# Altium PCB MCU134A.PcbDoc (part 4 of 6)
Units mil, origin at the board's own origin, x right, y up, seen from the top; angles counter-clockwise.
Board outline 4163.98 x 2693.8 mil, 6 copper layers (Top Layer, GND1, SIG1, PWR, GND2, Bottom), stack 58.132 mil thick; 218 components, 287 nets, 1260 pads, 770 vias.
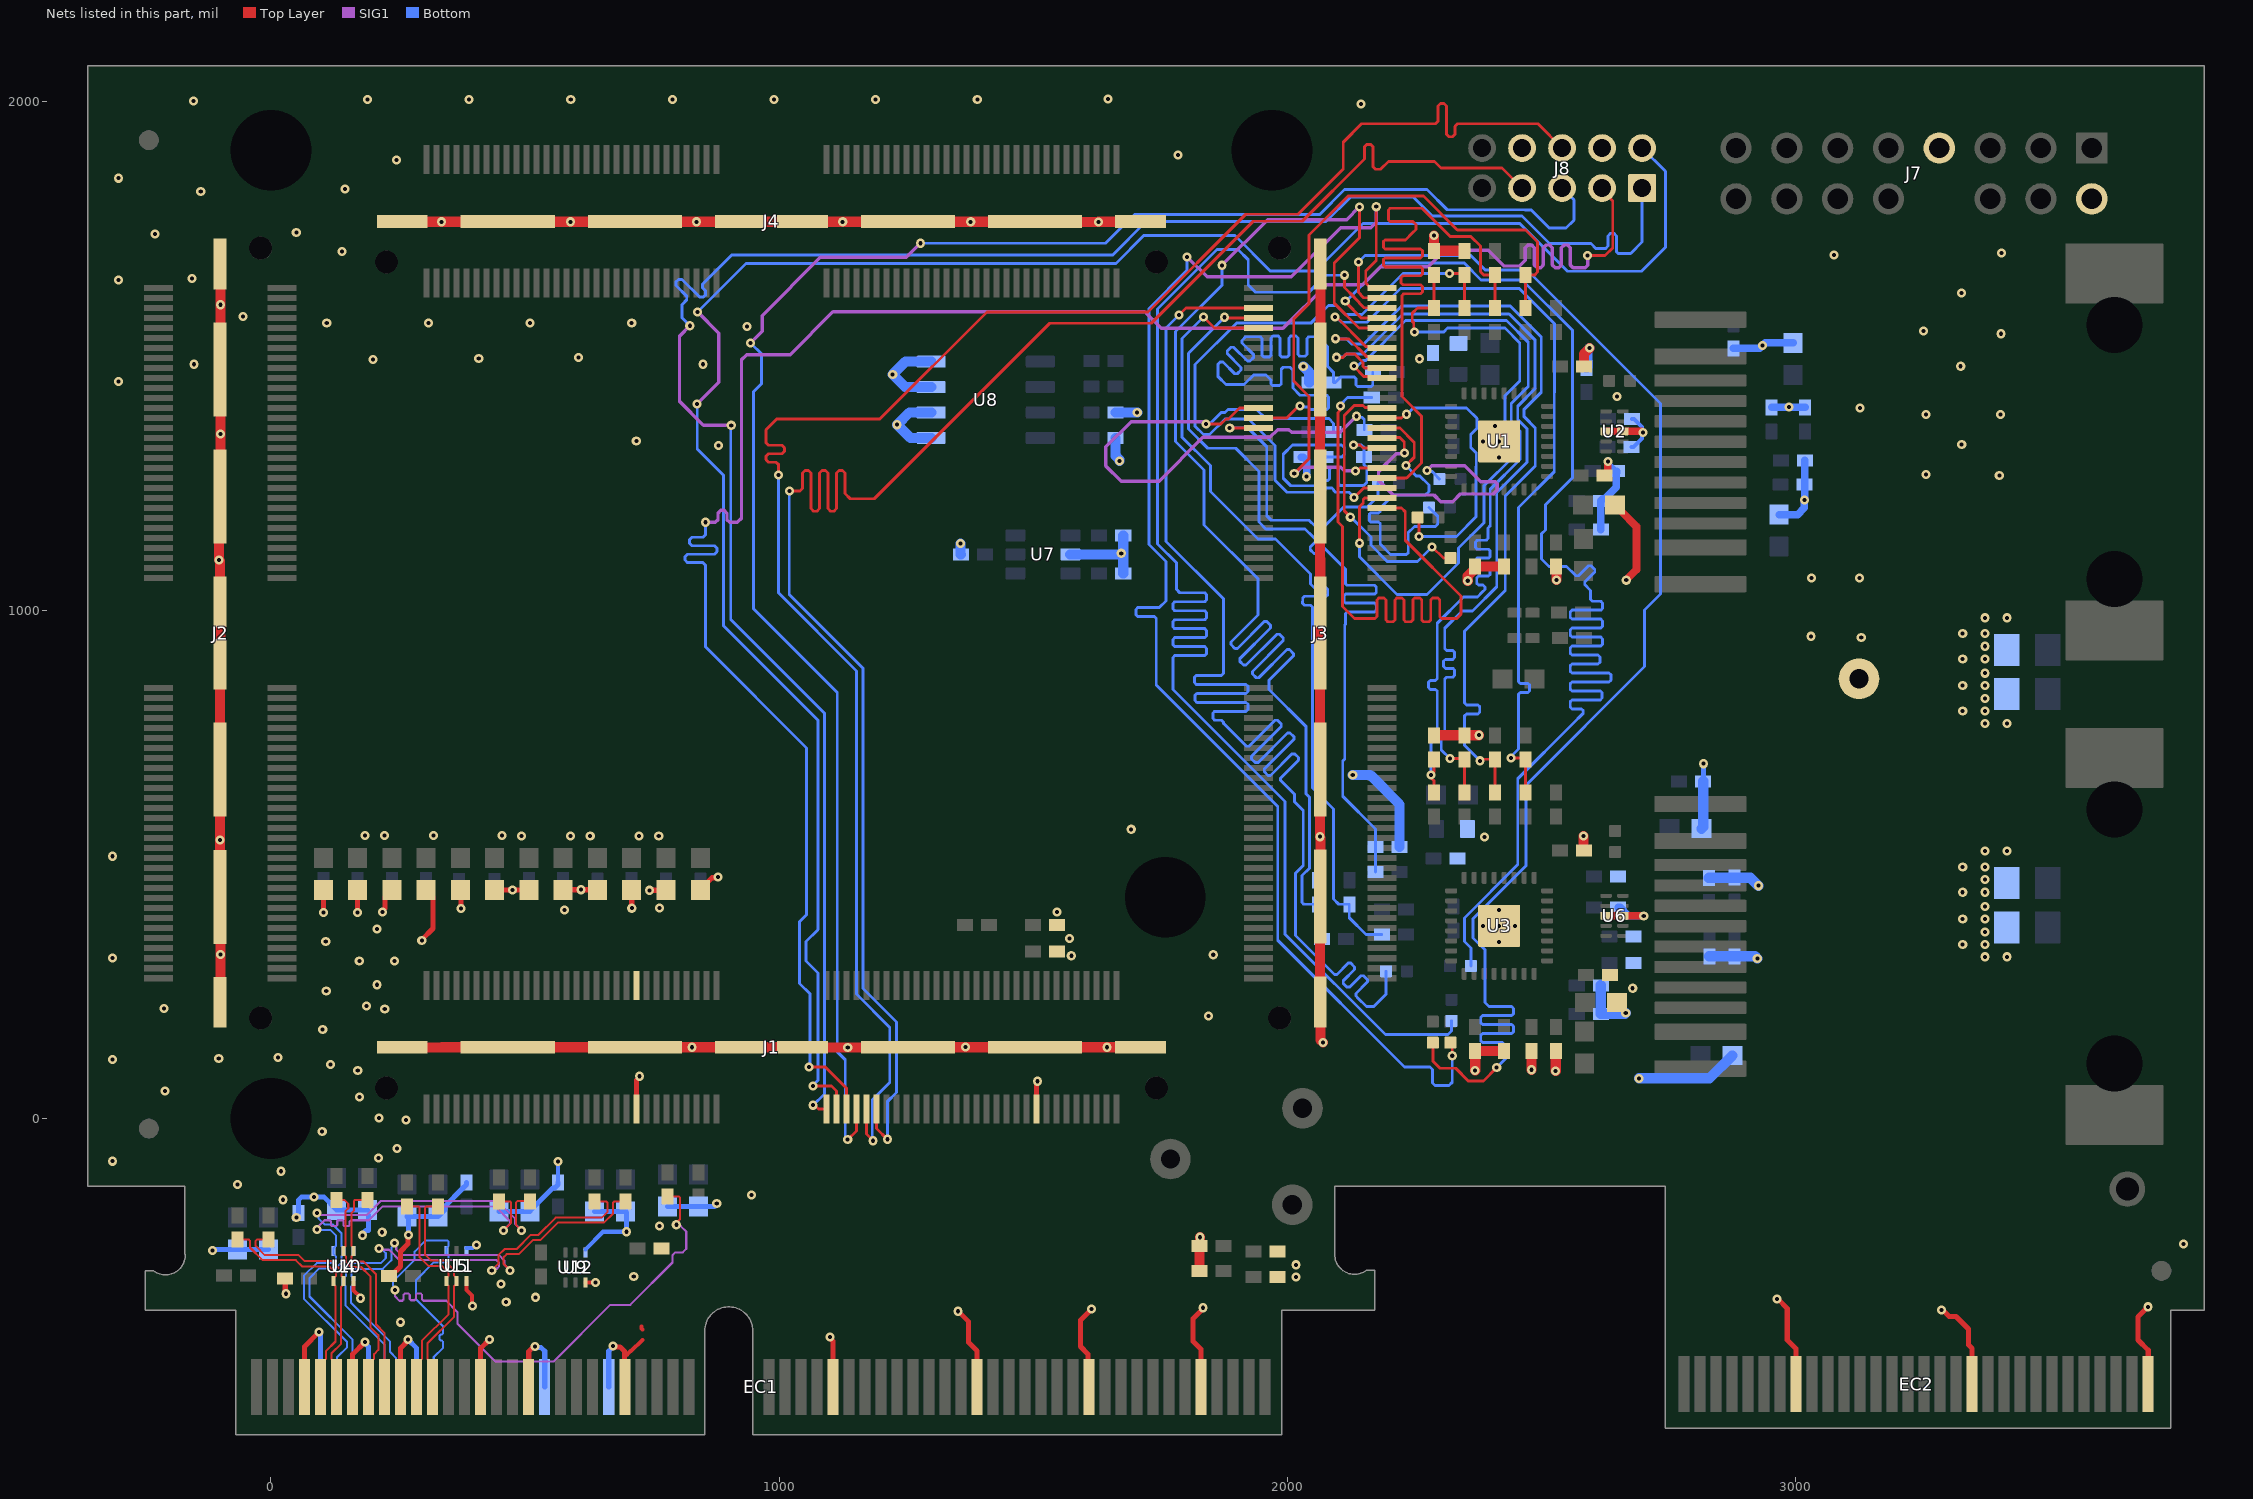
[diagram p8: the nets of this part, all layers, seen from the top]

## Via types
v1: diameter 18, hole 8, Top Layer to Bottom, tented both sides, 761 vias
v2: diameter 19.68, hole 7.87, Top Layer to Bottom, tented both sides, 9 vias

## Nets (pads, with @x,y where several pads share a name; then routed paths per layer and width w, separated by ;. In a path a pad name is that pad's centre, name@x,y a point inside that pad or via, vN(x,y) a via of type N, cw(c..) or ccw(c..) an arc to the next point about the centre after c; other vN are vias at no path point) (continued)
ESC_RX0_DATA0: J3.102 R78.1 R86.2 | length 1646.9
  Top Layer w5.66: v1(2131.17,1480.17) 2131.17,1479.24 2150.28,1460.14 2183.32,1460.14 J3.102@2186.5,1456.97 ; R78.1@2288.47,641.6 2289,642.12 2289,663.98 2283,669.98 2283,676.34 2289,682.34 2289,706.07 R86.2@2288.47,706.6
  Bottom w5.66: v1(2131.17,1480.17) 2133.54,1482.54 2140.02,1482.54 2149.11,1491.62 2154.5,1491.62 2232.87,1570 2431.3,1570 2474.18,1527.12 2474.18,1440.1 2440.76,1406.68 2440.76,1370.14 2458,1352.9 2458,1296.65 2399.37,1238.02 2399.37,1166.18 2394.87,1161.68 2394.87,1141.19 2391.34,1137.66 2373.77,1137.66 2370.24,1134.13 2370.24,1123.53 2373.77,1120 2395.66,1120 2399.19,1116.47 2399.19,1105.87 2395.66,1102.34 2373.77,1102.34 2370.24,1098.81 2370.24,1088.21 2373.77,1084.68 2395.66,1084.68 2399.19,1081.15 2399.19,1070.55 2395.66,1067.02 2376.36,1067.02 2372.83,1063.49 2372.83,1052.89 2376.36,1049.36 2385.3,1049.36 2388.84,1045.83 2388.84,1040.83 2383.29,1035.28 2374,1026 2346.65,1026 2294.99,974.35 2294.99,898.21 2294.99,865.43 2291.46,861.89 2281.44,861.89 2277.91,858.36 2277.91,847.77 2281.44,844.23 2291.46,844.23 2294.99,840.7 2294.99,837.87 2294.99,761.6 2283,749.61 v1(2283,675.99)
ESC_RX0_DATA1: J3.104 R70.1 R84.2 | length 1647.9
  Top Layer w5.66: v1(2097.1,1497.6) 2109.46,1497.6 2115.69,1503.83 2132.77,1503.83 2149,1487.59 2149,1479.97 2152.32,1476.65 J3.104@2186.5,1476.65 ; v1(2320,708) 2347.07,708 R84.2@2348.47,706.6 R70.1@2348.47,641.6
  Bottom w5.66: v1(2097.1,1497.6) 2098.27,1498.77 2110.63,1498.77 2116.14,1504.28 2149.25,1504.28 2227.63,1582.66 2436.55,1582.66 2487.03,1532.18 2487.03,1434.96 2453.42,1401.36 2453.42,1375.38 2472,1356.81 2472,1291.61 2412.03,1231.64 2412.03,1046.12 2364.59,998.68 2343.87,998.68 2309.7,964.51 2309.7,927.28 2309.7,924.45 2313.23,920.92 2325.57,920.92 2329.1,917.39 2329.1,906.79 2325.57,903.26 2311.19,903.26 2307.65,899.73 2307.65,889.13 2311.19,885.6 2325.57,885.6 2329.1,882.07 2329.1,871.47 2325.57,867.94 2313.23,867.94 2309.7,864.41 2309.7,833.64 2309.7,752.55 2303.04,745.88 2303.04,724.96 v1(2320,708)
ESC_RX0_DATA2: J3.106 R63.1 R71.1 | length 1645.9
  Top Layer w5.66: v1(2095,1534.26) 2095.93,1533.33 2121.64,1533.33 2155.46,1499.51 2183.32,1499.51 J3.106@2186.5,1496.34 ; v1(2379,703.68) 2382.34,703.68 2385.25,706.6 R63.1@2408.47,706.6 R71.1@2408.47,641.6
  Bottom w5.66: v1(2095,1534.26) 2095.93,1533.33 2117.03,1533.33 2126.24,1524.11 2151.18,1524.11 2225.98,1598.91 2438.2,1598.91 2499.69,1537.42 2499.69,1429 2466.08,1395.4 2466.08,1380.63 2488,1358.71 2488,1283.6 2428.83,1224.43 2428.83,1038.91 2419.49,1029.57 2419.49,1029.39 2349,958.9 2349,819.98 2349,817.15 2352.53,813.62 2375.08,813.62 2378.61,810.09 2378.61,799.49 2375.08,795.96 2352.53,795.96 2349,792.43 2349,788.66 2349,733.68 v1(2379,703.68)
ESC_RX0_DATA3: J3.108 R62.1 R72.1 | length 1628.1
  Top Layer w5.66: v1(2093.76,1576.74) 2096.86,1576.74 2154.42,1519.18 2183.34,1519.18 J3.108@2186.5,1516.02 ; v1(2440,709) 2462.49,709 2468.47,703.02 R72.1@2468.47,641.6
  Bottom w5.66: v1(2093.76,1576.74) 2097.1,1576.74 2107.31,1566.53 2156.59,1566.53 2222.92,1632.87 2456.41,1632.87 2525.56,1563.72 2525.56,1428.32 2525.19,1427.96 2525.19,1272.25 2455,1202.05 2455,862.2 2455,859.37 2458.53,855.84 2473.36,855.84 2476.89,852.31 2476.89,841.71 2473.36,838.18 2458.53,838.18 2455,834.65 2455,819.98 2455,785.34 2455,727 2440,712 v1(2440,709)
ESC_RX0_DV: J3.113 R68.1 R85.2 | length 1691.2
  Top Layer w5.66: v1(1876.53,1576.48) 1877.93,1575.09 J3.113@1943.5,1575.08
  Bottom w5.66: v1(1876.53,1576.48) 1805.51,1505.46 1805.51,1356.49 1843.38,1318.62 1898.68,1318.62 1944.24,1273.07 1944.24,1173.51 1957.74,1160 2035.13,1160 2049.97,1145.16 2055.6,1139.53 2055.6,1134.54 2045.12,1124.06 2045.12,1119.07 2052.62,1111.58 2057.61,1111.58 2068.08,1122.05 2073.08,1122.05 2075.08,1120.05 2114.2,1080.93 2114.2,1064.8 2114.2,1052.71 2117.73,1049.18 2171.46,1049.18 2174.99,1045.65 2174.99,1035.05 2171.46,1031.52 2114.75,1031.52 2111.22,1027.99 2111.22,1017.39 2114.75,1013.86 2171.46,1013.86 2174.99,1010.33 2174.99,999.73 2171.46,996.2 2117.73,996.2 2114.2,992.67 2114.2,972.18 2113.12,971.1 2113.12,707.31 2109.03,703.22 2109.03,679.76 2109,634 2173.68,569.32 R85.2@2173.68,534.38 2173.24,533.93 R68.1@2173.24,485.04
ESC_RX0_ERR: J3.111 R61.1 R73.1 | length 1649.7
  Top Layer w5.66: v1(1835.24,1576.87) 1856.72,1555.39 J3.111@1943.5,1555.39
  Bottom w5.66: v1(1835.24,1576.87) 1792.85,1534.48 1792.85,1340.42 1848.8,1284.46 1848.8,1233.83 1942.64,1140 1976.68,1140 2045.53,1071.14 2045.53,1051.65 2048.4,1048.78 2048.8,1048.38 2052.29,1044.8 2076.2,1044.5 2079.69,1040.93 2079.56,1030.33 2075.98,1026.84 2033.95,1027.37 2030.38,1023.88 2030.25,1013.28 2033.73,1009.71 2046.29,1009.55 2049.78,1005.98 2049.78,1003.15 2049.78,650.22 2091,609 2091,431.63 2101.25,421.38 R61.1@2122,421.38 2122,394.76 2155.05,361.72 R73.1@2185.9,361.72
ESC_RX1_CLK: J3.76 R9.1 | length 1338.3
  Top Layer w5.66: v1(2105,1402.03) 2102.64,1399.67 2102.64,1391.76 2099.51,1388.63 2099.51,1173.78 2108.91,1164.38 2108.91,1007.26 2132.39,983.77 2162.46,983.77 2172.83,983.77 2176.36,987.31 2176.36,1020.24 2179.89,1023.77 2190.49,1023.77 2194.02,1020.24 2194.02,980.85 2197.55,977.32 2208.15,977.32 2211.68,980.85 2211.68,1020.24 2215.21,1023.77 2225.81,1023.77 2229.34,1020.24 2229.34,980.85 2232.87,977.32 2243.47,977.32 2247,980.85 2247,1020.24 2250.53,1023.77 2261.13,1023.77 2264.66,1020.24 2264.66,980.85 2268.19,977.32 2278.79,977.32 2282.32,980.85 2282.32,1020.24 2285.85,1023.77 2296.45,1023.77 2299.98,1020.24 2299.98,987.31 2303.51,983.77 2324,983.77 2333.58,983.77 2342,992.2 2342,1027.73 2232.17,1137.56 2232.17,1193.73 2224.84,1201.06 J3.76@2186.5,1201.06
  Bottom w5.66: v1(2105,1402.03) 2105,1405 2118.51,1418.51 R9.1@2166.16,1418.51
ESC_RX1_DATA0: J3.78 R24.1 R31.2 | length 1274.5
  Top Layer w5.66: v1(2141.82,1131.82) 2141.82,1203.42 2149.41,1211.01 2149.41,1217.92 2152.24,1220.75 J3.78@2186.5,1220.75 ; v1(2250.44,1547.6) 2248.7,1549.34 2248.7,1565.57 2245.87,1568.4 2245.87,1584.44 2256.31,1594.88 R24.1@2288.47,1594.88 R31.2@2288.47,1659.88
  Bottom w5.66: v1(2141.82,1131.82) 2141.82,1105.19 2216,1031 2275,1031 2337.17,1093.17 2337.17,1122.17 2386.71,1171.71 2386.71,1244.16 2444,1301.46 2444,1349 2428.1,1364.9 2428.1,1421.9 2457.44,1451.23 2457.44,1525.96 2428.4,1555 2315.33,1555 2307.93,1547.6 v1(2250.44,1547.6)
ESC_RX1_DATA1: J3.80 R15.1 R29.2 | length 1313.5
  Top Layer w5.66: v1(2131.58,1221.72) 2150.29,1240.43 J3.80@2186.5,1240.43 ; v1(2319.14,1662.33) 2346.02,1662.33 R29.2@2348.47,1659.88 R15.1@2348.47,1594.88
  Bottom w5.66: v1(2131.58,1221.72) 2121.19,1232.12 2115.45,1232.12 2094.96,1232.12 2091.42,1235.65 2091.42,1236.7 2087.89,1240.23 2077.3,1240.23 2073.76,1236.7 2073.76,1235.65 2070.23,1232.12 2064.32,1232.12 1999.28,1232.12 1975.54,1255.86 1975.54,1324.31 1923.5,1376.34 1877.96,1376.34 1847.11,1345.49 1834.96,1345.49 1818.51,1361.94 1818.51,1483.38 1899.88,1564.75 2046.13,1564.75 2080.82,1599.43 2096.28,1599.43 2113.85,1581.86 2147.26,1581.86 2227.73,1662.33 v1(2319.14,1662.33)
ESC_RX1_DATA2: J3.82 R8.1 R16.1 | length 1392.8
  Top Layer w5.66: J3.82@2186.5,1260.12 2234.9,1260.12 2264.35,1289.56 2264.35,1381.62 2225.64,1420.34 2225.64,1598.63 2225.64,1619.13 2229.17,1622.66 2262.38,1622.66 2265.91,1626.19 2265.91,1636.79 2262.38,1640.32 2227.4,1640.32 2223.87,1643.85 2223.87,1654.45 2227.4,1657.98 2262.38,1657.98 2265.91,1661.51 2265.91,1672.11 2262.38,1675.64 2192.47,1675.64 2188.94,1679.17 2188.94,1689.77 2192.47,1693.3 2262.38,1693.3 2265.91,1696.83 2265.91,1707.43 2262.38,1710.96 2192.47,1710.96 2188.94,1714.49 2188.94,1725.09 2192.47,1728.62 2232.36,1728.62 2246.38,1742.64 2253,1749.26 2253,1759 2247,1765 2202.32,1765 2199,1768.32 2199,1787.68 2202.32,1791 2265,1791 2320.49,1735.51 2361.01,1735.51 2380,1716.51 2380,1666.11 2386.24,1659.88 R8.1@2408.47,1659.88 R16.1@2408.47,1594.88
ESC_RX1_DATA3: J3.84 R7.1 R17.1 | length 1358.6
  Top Layer w5.66: v1(2013.69,1268.92) 2042.83,1298.06 2042.83,1420.79 2012.67,1450.95 2012.67,1572.67 2042.83,1602.83 2042.83,1737.99 2119.9,1815.06 2267.68,1815.06 2334.58,1748.17 2468.83,1748.17 2492.62,1724.38 2492.62,1665.39 2487.11,1659.88 R7.1@2468.47,1659.88 R17.1@2468.47,1594.88 ; v1(2133.97,1274.04) 2137.31,1274.04 2143.07,1279.8 J3.84@2186.5,1279.8
  SIG1 w6.66: v1@2013.97,1268.92 2016.76,1268.92 2028.82,1280.98 2105.21,1280.98 2112.14,1274.04 v1(2133.97,1274.04)
ESC_RX1_DV: J3.93 R13.1 R30.2 | length 1335.9
  Top Layer w5.66: J3.93@1943.5,1378.23 1998.87,1378.23 2022.75,1402.12 v1(2025,1402.12)
  Bottom w5.66: v1(2025,1402.12) 2027.36,1399.76 2040.56,1399.76 2045.32,1395 2077.68,1395 2081,1398.32 2081,1419.68 2077.68,1423 2025,1423 2011,1437 2011,1472 2005,1478 1992,1478 1988,1474 1988,1445.25 1984.68,1441.94 1971.32,1441.94 1968,1445.25 1968,1453 1958.04,1462.96 1933.96,1462.96 1915,1444 1879.32,1444 1864,1459.32 1864,1468.7 1864,1484.34 1864.64,1484.98 1868.17,1488.51 1873.17,1488.51 1896.46,1465.22 1901.45,1465.22 1908.94,1472.71 1908.94,1477.71 1881.76,1504.89 1881.76,1509.88 1889.26,1517.37 1894.25,1517.37 1921.43,1490.2 1926.43,1490.2 1933.92,1497.69 1933.92,1502.68 1910.63,1525.97 1910.63,1530.97 1917.66,1538 1926.28,1538 1946.77,1538 1950.3,1534.47 1950.3,1501.53 1953.83,1498 1964.43,1498 1967.96,1501.53 1967.96,1535.89 1971.49,1539.43 1982.09,1539.43 1985.62,1535.89 1985.62,1501.53 1989.15,1498 1999.75,1498 2003.28,1501.53 2003.28,1535.89 2006.81,1539.43 2017.41,1539.43 2020.94,1535.89 2020.94,1503.12 2024.47,1499.59 2035.07,1499.59 2038.6,1503.12 2038.6,1534.47 2042.13,1538 2060,1538 2063,1535 2078.88,1519.12 2078.88,1479.97 2090.55,1468.3 R30.2@2090.55,1448 2094.49,1448 2105.25,1458.75 2131.68,1458.75 2135,1455.44 2135,1442.83 2137.83,1440 2165.4,1440 2168.23,1442.83 R13.1@2168.23,1468.23
ESC_RX1_ERR: J3.95 R6.1 R18.1 | length 1265.7
  Top Layer w5.66: v1(1840.06,1366.3) 1869.22,1366.3 1879.25,1376.34 1884.51,1376.34 1906.03,1397.86 J3.95@1943.46,1397.86
  SIG1 w6.66: v1(1840.06,1366.3) 1835.59,1370.78 1692.59,1370.78 1643.1,1321.29 1643.1,1283.76 1672.81,1254.04 1747.91,1254.04 1834.05,1340.18 1965.86,1340.18 1980.96,1355.28 2003,1355.28 2008.44,1349.84 2103.84,1349.84 2135.6,1381.6 v1(2136.41,1381.6)
  Bottom w5.66: v1(1840.06,1366.3) 1847.38,1366.3 1870.08,1389 1877.53,1389 1883.53,1395 1939.61,1395 1957.56,1377.06 2081.75,1377.06 2091.18,1367.62 R6.1@2091.18,1350.43 ; v1(2136.41,1381.6) 2138.37,1379.64 2146.83,1379.64 2151.46,1375.01 R18.1@2151.46,1354.96
ESC_TX0_CLK: J3.112 R74.1 R83.2 | length 2694.6
  Top Layer w5.66: v1(2141.96,1793.67) 2141.96,1732.85 2092.31,1683.2 2092.31,1603.91 2140.82,1555.39 J3.112@2186.5,1555.39
  SIG1 w6.66: v1(1871.38,1678.62) 1961.13,1768.38 2116.66,1768.38 v1(2141.96,1793.67)
  Bottom w5.66: v1(1871.38,1678.62) 1871.38,1639.46 1780.19,1548.27 1780.19,1331.81 1836.14,1275.86 1836.14,1167.86 1942.16,1061.84 1942.16,990.25 1889.27,937.36 1889.27,932.36 1896.76,924.87 1901.75,924.87 1954.65,977.76 1959.64,977.76 1967.13,970.27 1967.13,965.27 1906.36,904.5 1906.36,899.5 1913.85,892.01 1918.84,892.01 1979.62,952.79 1984.62,952.79 1992.11,945.29 1992.11,940.3 1931.33,879.52 1931.33,874.53 1938.82,867.03 1943.82,867.03 1999.35,922.57 2004.35,922.57 2011.84,915.08 2011.84,910.08 1964.04,862.28 1964.04,843.79 2037.12,770.71 2037.12,638.12 2043.99,631.25 2043.99,492.66 2029,477.67 2029,424.69 2032.32,421.38 R83.2@2060,421.38 2060,391 2068.61,382.4 R74.1@2068.61,352.87
ESC_TX0_DATA0: J3.114 R69.2 | length 2834.9
  Top Layer w5.66: v1(2114.01,1608.33) 2114.01,1606.8 2145.62,1575.19 2150.96,1575.19 2151.07,1575.08 J3.114@2186.5,1575.08
  Bottom w5.66: v1(2114.01,1608.33) 2116.12,1608.33 2191.31,1683.52 2347.48,1683.52 2381.15,1649.85 2462.04,1649.85 2560.85,1551.04 2560.85,1260.4 2507.83,1207.37 2507.83,1158 2500.28,1150.45 2500.28,1100.72 2514.99,1086.01 2549.54,1086.01 2565.78,1069.76 2567.79,1067.76 2572.78,1067.76 2592.41,1087.38 2597.4,1087.38 2604.89,1079.89 2604.89,1074.9 2585.27,1055.27 2585.27,1050.28 2596.69,1038.85 2596.69,1024.06 2596.69,1021.23 2600.23,1017.69 2616.67,1017.69 2620.21,1014.16 2620.21,1003.57 2616.67,1000.03 2560.23,1000.03 2556.69,996.5 2556.69,985.91 2560.23,982.37 2616.67,982.37 2620.21,978.84 2620.21,968.25 2616.67,964.71 2560.23,964.71 2556.69,961.18 2556.69,950.59 2560.23,947.05 2616.67,947.05 2620.21,943.52 2620.21,932.93 2616.67,929.39 2560.23,929.39 2556.69,925.86 2556.69,915.27 2560.23,911.73 2611.5,911.73 2615.04,908.2 2615.04,897.61 2611.5,894.07 2560.23,894.07 2556.69,890.54 2556.69,879.95 2560.23,876.41 2633.16,876.41 2636.69,872.88 2636.69,862.29 2633.16,858.75 2560.23,858.75 2556.69,855.22 2556.69,844.63 2560.23,841.09 2616,841.09 2619.53,837.56 2619.53,826.97 2616,823.43 2560.23,823.43 2556.69,819.9 2556.69,809.31 2560.23,805.77 2578.72,805.77 2582.25,802.24 2582.25,797.25 2560.17,775.17 2453.51,668.51 2453.51,499.32 2348.6,394.4 2348.6,348 2361.34,335.26 R69.2@2361.34,300
ESC_TX0_DATA1: J3.116 R67.2 | length 2866.8
  Top Layer w5.66: v1(2112.51,1659.17) 2112.51,1635.05 2131.84,1615.72 2131.84,1615.04 2141.48,1605.4 2141.48,1604.72 2151.12,1595.08 2186.18,1595.08 J3.116@2186.5,1594.76
  Bottom w5.66: v1(2112.51,1659.17) 2075.62,1659.17 2042.05,1625.6 1937.4,1625.6 1923.14,1639.86 1923.14,1689.47 1902.68,1709.93 1861.65,1709.93 1744.58,1592.87 1744.58,1130.44 1782.33,1092.69 1782.33,1040.51 1788.53,1034.3 1837.61,1034.3 1841.14,1030.77 1841.14,1020.17 1837.61,1016.64 1778.53,1016.64 1775,1013.11 1775,1002.51 1778.53,998.98 1837.61,998.98 1841.14,995.45 1841.14,984.85 1837.61,981.32 1778.53,981.32 1775,977.79 1775,967.19 1778.53,963.66 1837.61,963.66 1841.14,960.13 1841.14,949.53 1837.61,946 1778.53,946 1775,942.47 1775,931.87 1778.53,928.34 1837.61,928.34 1841.14,924.81 1841.14,914.21 1837.61,910.68 1778.53,910.68 1775,907.15 1775,844.2 1995.67,623.53 1995.67,362.23 2192.93,164.98 2315.98,164.98 2323.1,172.1 R67.2@2323.1,192.09
ESC_TX0_DATA2: J3.118 R66.2 | length 2769.5
  Top Layer w5.66: v1(2140,1685) 2140,1625.46 2144.5,1620.96 2144.5,1620.28 2149.95,1614.83 J3.118@2186.11,1614.83 ; R66.2@2286.32,149.04 2286.32,112.68 2300.34,98.66 2331.32,98.66 2356.08,73.91 2385.91,73.91 v1(2412,100)
  Bottom w5.66: v1(2140,1685) 2153.05,1698.05 2360.95,1698.05 2389.49,1669.51 2471.49,1669.51 2734.56,1406.44 2734.56,1031.73 2703,1000.17 2703,889 2470,656 2470,497.45 2365.58,393.03 2365.58,355.04 2388.79,331.82 2388.79,228.21 2396.95,220.05 2441.47,220.05 2445,216.52 2445,205.92 2441.47,202.39 2384.19,202.39 2380.66,198.86 2380.66,188.26 2384.19,184.73 2441.47,184.73 2445,181.2 2445,170.6 2441.47,167.07 2384.19,167.07 2380.66,163.54 2380.66,152.94 2384.19,149.41 2423.31,149.41 2429.71,143.01 2429.71,117.86 2412,100.15 v1(2412,100)
ESC_TX0_DATA3: J3.120 R65.2 | length 2792.5
  Top Layer w5.66: v1(2175,1794) 2175,1688.38 2154.26,1667.65 2154.26,1643.83 2163.96,1634.13 J3.120@2186.5,1634.13 ; R65.2@2320.94,149.12 2324.57,145.49 v1(2324.57,123.35)
  SIG1 w6.66: v1(1802.57,1695.31) 1842.1,1655.78 2008.09,1655.78 2105.06,1752.75 2164.35,1752.75 2175,1763.4 v1(2175,1794)
  Bottom w5.66: v1(1802.57,1695.31) 1802.76,1695.12 1802.76,1668.95 1727.6,1593.79 1727.6,1129.52 1761.09,1096.03 1761.09,1018.04 1748.07,1005.02 1705.6,1005.02 1702.07,1001.49 1702.07,990.89 1705.6,987.36 1738.54,987.36 1742.07,983.83 1742.07,853.12 1981.16,614.03 1981.16,350.7 2230.44,101.42 2280.71,101.42 2285.71,96.42 2285.71,69.71 2290.71,64.71 2318.07,64.71 2324.57,71.22 v1(2324.57,123.35)
ESC_TX0_ENA: J3.115 R60.2 | length 2823.5
  Top Layer w5.66: v1(1787,1581) 1800.7,1594.7 J3.115@1943.44,1594.7
  Bottom w5.66: v1(1787,1581) 1761.56,1555.56 1761.56,1135.44 1874.11,1022.89 1874.11,892.49 1874.11,875.19 1870.58,871.66 1820.81,871.66 1817.28,868.13 1817.28,857.53 1820.81,854 1918.87,854 1922.4,850.47 1922.4,839.87 1918.87,836.34 1821.96,836.34 1818.42,832.81 1818.42,822.21 1821.96,818.68 1918.87,818.68 1922.4,815.15 1922.4,804.55 1918.87,801.02 1857.28,801.02 1853.74,797.49 1853.74,786.89 1857.28,783.36 1870.58,783.36 1874.11,779.83 1874.11,777.72 1874.83,777 1917.52,734.31 1919.52,732.31 1924.52,732.31 1975.64,783.43 1980.63,783.43 1988.13,775.94 1988.13,770.94 1929.64,712.46 1929.64,707.46 1937.14,699.97 1942.13,699.97 2000.61,758.46 2005.61,758.46 2013.1,750.96 2013.1,745.97 1954.62,687.48 1954.62,682.49 1962.11,675 1967.11,675 2009.47,717.36 2014.47,717.36 2021.96,709.87 2021.96,704.88 1986.95,669.87 1986.95,664.87 1993.91,657.91 2014,637.83 2014,623.11 2031.33,605.77 2031.33,497.9 2016,482.57 2016,359.81 2090.62,285.19 2092.62,283.18 2097.62,283.18 2120.02,305.59 2125.02,305.59 2132.51,298.1 2132.51,293.1 2110.11,270.7 2110.11,265.7 2117.6,258.21 2122.59,258.21 2145,280.62 2149.99,280.62 2157.49,273.12 2157.49,268.13 2135.08,245.72 2135.08,240.73 2138.24,237.57 2155.81,220 2170,220 2194.37,244.37 R60.2@2194.37,289.55
ESC_TX1_CLK: J3.88 R20.1 R28.2 | length 613.7
  Top Layer w5.66: v1(2130,1325) 2143.17,1325 2149,1319.17 J3.88@2186.5,1319.17
  Bottom w5.66: R28.2@2075.03,1301.32 2107.11,1301.32 2111.97,1306.17 2111.97,1319.83 2106.55,1325.24 2010.24,1325.24 1991.93,1306.93 1991.93,1259.52 2006.67,1244.78 2055.71,1244.78 2065.93,1255 2079.57,1255 2083.1,1258.53 2083.1,1277.48 2086.63,1281.02 2097.23,1281.02 2100.76,1277.48 2100.76,1248.78 2104.29,1245.25 2150.49,1245.25 2156.25,1251.01 2156.25,1280.89 2150.55,1286.58 R20.1@2150.55,1301.83 2150.55,1320.7 2146.25,1325 v1(2130,1325)
ESC_TX1_DATA0: J3.90 R14.2 | length 614.5
  Top Layer w5.66: J3.90@2186.5,1338.86 2187.51,1339.88 2221.32,1339.88 2230.02,1331.17 2230.02,1310.35 v1@2230.66,1309.7
  SIG1 w6.66: v1(2230.66,1309.24) 2229.51,1308.09 2214.64,1308.09 2179.45,1272.9 2179.45,1256.02 2208.79,1226.67 2288.65,1226.67 2301.65,1213.66 2325.21,1213.66 2340.19,1228.64 2405.17,1228.64 2413,1236.47 2413,1249.12 2409.1,1253.02 2380.45,1253.02 2349.45,1284.02 2284.57,1284.02 2275.55,1275 v1(2275,1275)
  Bottom w5.66: v1@2274.17,1275.83 v1(2275,1275) 2277.36,1272.64 2285.2,1272.64 2290.43,1267.42 2290.43,1266.95 2298.94,1258.44 R14.2@2299.41,1258.44
ESC_TX1_DATA1: J3.92 R12.2 | length 626.7
  Top Layer w5.66: J3.92@2186.5,1358.54 2221.46,1358.54 2249.85,1330.15 2249.85,1300.85 2233.51,1284.51 v1(2233.51,1284.4)
  Bottom w5.66: v1(2233.51,1284.4) 2253.84,1264.07 2260.71,1264.07 2278.68,1246.1 2278.68,1233.68 2272,1227 2209,1227 2183,1201 2183,1194.82 2179.68,1191.5 2164.07,1191.5 2161.42,1188.85 2161.42,1176.49 2164.07,1173.84 2179.68,1173.84 2183,1170.53 2183,1167.7 2183,1130 2203.19,1109.81 2234.68,1109.81 2238,1113.12 2238,1153 2250,1165 2291.49,1165 2296.01,1169.52 2296.01,1184.81 R12.2@2278.68,1202.13
ESC_TX1_DATA2: J3.94 R11.2 | length 573.6
  Top Layer w5.66: J3.94@2186.5,1378.23 2224.89,1378.23 2232.28,1385.62 v1(2234.38,1385.62) ; R11.2@2256.49,1182.57 2259,1180.06 v1(2259,1145)
  Bottom w5.66: v1(2234.38,1385.62) 2235.62,1385.62 2247.79,1397.79 2352.88,1397.79 2355.56,1395.1 2373.12,1377.54 2373.12,1358.12 2361,1346 2361,1319.93 2371.76,1309.18 2371.76,1282.55 2371.58,1282.37 2371.58,1183.97 2332.81,1145.2 2259.2,1145.2 v1(2259,1145)
ESC_TX1_DATA3: J3.96 R10.2 | length 553
  Top Layer w5.66: v1(2123.99,1182.99) 2123.99,1183.85 2112.17,1195.66 2112.17,1383.39 2131.69,1402.9 2148.52,1402.9 2152.78,1398.65 2185.73,1398.65 J3.96@2186.5,1397.91 ; v1(2285,1124.63) 2307.23,1102.4 R10.2@2320.94,1102.4
  Bottom w5.66: v1(2123.99,1182.99) 2125.48,1182.99 2164.41,1144.06 2164.41,1128.21 2196.51,1096.12 2256.49,1096.12 v1(2285,1124.63)
ESC_TX1_ENA: J3.91 R5.2 | length 558.4
  Top Layer w5.66: v1(1886.64,1358.51) 1942.65,1358.53 J3.91@1942.86,1358.74
  Bottom w5.66: v1(1886.64,1358.51) 1887.06,1358.93 1922.06,1358.93 1959.56,1321.44 1959.56,1185.85 1968.4,1177 2043,1177 2055.25,1164.75 2072.81,1164.75 2110.96,1202.89 2157.26,1202.89 2178.11,1223.75 R5.2@2178.11,1249.88
FSIRX_CLK: J1.55 J8.3 | length 4108.2
  Top Layer w5.66: v1(1058.64,101) 1091,101 1132.64,59.36 J1.55@1132.64,18.5 ; v1(2590.78,1697.65) 2625.15,1697.65 2640.28,1712.79 2640.28,1805.45 2619.45,1826.29 J8.3@2619.45,1830.63
  SIG1 w6.66: v1(855,1173) 874.49,1173 879.79,1178.3 879.79,1191.15 885.09,1196.45 892.15,1196.45 897.45,1191.15 897.45,1178.3 902.75,1173 918.07,1173 926,1180.93 926,1492.97 935.93,1502.9 1021.9,1502.9 1106,1587 1719.79,1587 1752.23,1554.56 1991.57,1554.56 2077.33,1640.32 2148.11,1640.32 2183.43,1675.64 2277.27,1675.64 2309.63,1708 2395.34,1708 2426,1677.34 2457.52,1677.34 2468.55,1688.38 2468.55,1713.25 2473.85,1718.55 2480.92,1718.55 2486.21,1713.25 2486.21,1679.26 2491.51,1673.97 2498.58,1673.97 2503.87,1679.26 2503.87,1713.25 2509.17,1718.55 2516.24,1718.55 2521.53,1713.25 2521.53,1679.26 2526.83,1673.97 2533.9,1673.97 2539.19,1679.26 2539.19,1713.25 2544.49,1718.55 2551.56,1718.55 2556.85,1713.25 2556.85,1679.26 2562.15,1673.97 2585.97,1673.97 2591,1679 2591,1697.43 v1(2590.78,1697.65)
  Bottom w5.66: v1(855,1173) 855,1148.5 850,1143.5 828.45,1143.5 823.45,1138.5 823.45,1131.84 828.45,1126.84 872.95,1126.84 877.94,1121.84 877.94,1115.18 872.95,1110.18 820,1110.18 815,1105.18 815,1098.52 820,1093.52 850,1093.52 855,1088.52 855,928.09 1054,729.09 1054,400.62 1040.28,386.89 1040.28,322.53 1040.34,322.47 1040.34,265.76 1060.69,245.41 1060.69,103.04 v1(1058.64,101)
FSIRX_D0: J1.59 J8.1 | length 4073.9
  Top Layer w5.66: v1(1067,26) 1070.34,26 1077.84,18.5 J1.59@1093.27,18.5
  SIG1 w6.66: v1(824.31,1559.69) 804,1539.37 804,1411 851.16,1363.84 v1(905.89,1363.84)
  Bottom w5.66: v1(824.31,1559.69) 809.27,1574.73 809.27,1601.73 818.36,1610.82 818.36,1617.89 797.15,1639.1 797.15,1646.17 801.86,1650.88 808.93,1650.88 843.78,1616.03 850.85,1616.03 855.56,1620.74 855.56,1627.81 848.99,1634.38 848.99,1641.45 906.13,1698.58 1655.77,1698.58 1722.1,1764.91 2076.14,1764.91 2123.93,1812.71 2248.17,1812.71 2285.54,1775.34 2461.93,1775.34 2515.91,1721.36 2597.28,1721.36 2607.26,1711.38 2626.17,1711.38 2631.16,1716.38 2631.16,1736.61 2636.16,1741.61 2642.83,1741.61 2647.82,1736.61 2647.82,1705.32 2651.14,1702 2675.62,1702 2698.19,1724.57 J8.1@2698.19,1830.63 ; v1(905.89,1363.84) 905.47,1363.84 905,1363.37 905,981.4 1089.13,797.27 1089.13,48.13 v1(1067,26)
FSIRX_D1: J1.57 J8.2 | length 4070.9
  Top Layer w5.66: v1(1067,64) 1103,64 1112.95,54.05 J1.57@1112.95,18.5
  SIG1 w6.66: v1(838.31,1405.69) 881,1448.37 881,1545.27 v1(839.5,1586.77)
  Bottom w5.66: v1@839,1405 839,1317.19 890.6,1265.58 890.6,969.43 1076.47,783.56 1076.47,371.35 1053,347.88 1053,309.44 1076.47,285.96 1076.47,75.17 1067,65.7 v1(1067,64) ; v1(839.5,1586.77) 934.72,1682 939.47,1682 1662.64,1682 1717.64,1737 1897.16,1737 1966.51,1667.65 2055.65,1667.65 2148.83,1760.83 2457.29,1760.83 2551.12,1667 2696.83,1667 2744,1714.17 2744,1863.57 J8.2@2698.19,1909.37
FSITX_CLK: J1.49 J8.7 | length 3631.9
  Top Layer w5.66: v1(1020.71,1234.8) 1041.16,1234.8 1046.15,1239.8 1046.15,1269.8 1051.15,1274.8 1057.82,1274.8 1062.81,1269.8 1062.81,1199.8 1067.81,1194.8 1074.48,1194.8 1079.47,1199.8 1079.47,1269.8 1084.47,1274.8 1091.14,1274.8 1096.13,1269.8 1096.13,1199.8 1101.13,1194.8 1107.8,1194.8 1112.79,1199.8 1112.79,1269.8 1117.79,1274.8 1124.46,1274.8 1129.45,1269.8 1129.45,1229.82 1140.1,1219.18 1187.18,1219.18 1532.61,1564.61 1732.14,1564.61 1932.97,1765.43 2029.33,1765.43 2151.92,1888.02 2151.92,1911.87 2156.3,1916.26 2164.16,1916.26 2168.58,1911.84 2168.58,1872.42 2173.29,1867.71 2183.51,1867.71 2198.89,1883.09 2289.4,1883.09 2302.49,1870 2422.61,1870 J8.7@2461.97,1830.63 ; J1.49@1191.69,18.5 1191.69,-19.69 v1(1213,-41)
  Bottom w5.66: v1@1020,1235 1020,1030.76 1165.09,885.67 1165.09,255.91 1231.33,189.67 1231.33,51.14 1213,32.81 v1(1213,-41)
FSITX_D0: J1.53 J8.5 | length 3600.2
  Top Layer w5.66: v1(1135.01,-41.17) 1135.84,-41.17 1152.32,-24.69 J1.53@1152.32,18.5
  SIG1 w6.66: v1(944,1526) 966.8,1548.8 966.8,1579.8 1081.13,1694.13 1250.13,1694.13 v1(1278,1722)
  Bottom w5.66: v1(944,1526) 965.76,1504.24 965.76,1446.29 950,1430.53 950,1002.6 1114.45,838.14 1114.45,131.17 1130.24,115.39 1130.24,-36.4 v1(1135.01,-41.17) ; v1(1278,1722) 1642.19,1722 1699.04,1778.85 2063.85,1778.85 2112.72,1827.72 2275.14,1827.72 2314.86,1788 2467.17,1788 2467.39,1787.78 2479.6,1787.78 2515.37,1752 2548.38,1752 2563.84,1767.47 2563.84,1807.5 J8.5@2540.71,1830.63
FSITX_D1: J1.51 J8.6 | length 3632.3
  Top Layer w5.66: v1(999.16,1265.89) 999.16,1286.18 994.16,1291.18 979.33,1291.18 974.33,1296.18 974.33,1302.84 979.33,1307.84 1005.66,1307.84 1010.66,1312.84 1010.66,1319.5 1005.66,1324.5 979.33,1324.5 974.33,1329.5 974.33,1354.9 995.43,1376 1198,1376 1409,1587 1726,1587 1918.18,1779.18 2021.17,1779.18 2110,1868.01 2110,1920.94 2146.16,1957.11 2291.5,1957.11 2296.5,1962.11 2296.5,1992.11 2301.5,1997.11 2308.16,1997.11 2313.16,1992.11 2313.16,1936.5 2318.16,1931.5 2324.82,1931.5 2329.82,1936.5 2329.82,1952.11 2334.82,1957.11 2492.98,1957.11 J8.6@2540.71,1909.37 ; J1.51@1172.01,18.5 1172.01,-30.59 1184.73,-43.31 v1(1184.73,-44)
  Bottom w5.66: v1(999.16,1265.89) 999.16,1033.7 1152.43,880.42 1152.43,244.57 1217.83,179.17 1217.83,70.61 1183.33,36.11 1183.33,-42.6 v1(1184.73,-44)
GND: C1.2 C2.2 C3.2 C4.1 C5.1 C6.1 C7.1 C8.2 C9.2 C10.2 C11.2 C12.2 C13.2 C14.1 C15.2 C16.2 C17.1 C18.2 C19.2 C20.2 C21.2 C22.2 C23.2 C24.2 C26.2 C32.2 C33.2 C34.2 C35.2 C36.2 C37.2 C41.2 C42.2 C43.1 C44.1 C45.1 C46.1 C47.2 C48.2 C49.2 C50.2 C59.2 C60.2 C61.2 C62.2 C63.2 C64.2 C65.2 C66.2 C67.2 C68.2 C69.2 C70.2 C71.2 C72.2 C73.2 C74.2 C75.2 C76.2 C77.2 C78.2 C79.2 C80.2 C81.2 C82.2 C83.2 C84.2 C85.2 EC1.7 EC1.10 EC1.13 EC1.16 EC1.19 EC1.22 EC1.29 EC1.35 EC1.38 EC1.46 EC1.47 EC1.65 EC1.83 EC1.97 EC1.111 EC2.135 EC2.157 EC2.179 J1.17 J1.77 J1.78 J1.A1 J1.A2 J1.A3 J1.A4 J1.A5 J1.A6 J1.A7 J1.A8 J2.A1 J2.A2 J2.A3 J2.A4 J2.A5 J2.A6 J2.A7 J2.A8 J3.A1 J3.A2 J3.A3 J3.A4 J3.A5 J3.A6 J3.A7 J3.A8 J4.A1 J4.A2 J4.A3 J4.A4 J4.A5 J4.A6 J4.A7 J4.A8 J7.2 J7.7 J8.4 J8.8 R1.2 R4.1 R25.1 R26.1 R27.1 R28.1 R29.1 R30.1 R31.1 R33.1 R34.1 R38.1 R56.2 R59.1 R79.1 R80.1 R81.1 R82.1 R83.1 R84.1 R85.1 R86.1 R87.1 R88.1 R89.1 R94.2 R95.2 R96.2 TP4.1 U1.33 U2.3@2627.29,1352 U2.8@2660.16,1352 U3.33 U4.3 U5.3 U6.3@2627.29,398.72 U6.8@2660.16,398.72 U7.2 U8.1 U8.2 U8.3 U8.4 U9.3 U10.3 U11.3 U12.3 | length 13319.8
  Top Layer w8: U4.3@162.96,-320.41 162.96,-338.25 176.26,-351.55 v1(176.26,-353.88) ; U5.3@384.69,-319.53 384.69,-337.37 395.41,-348.1 395.41,-367.48 v1(397.03,-369.1) ; U9.3@619.03,-322.66 619.03,-322.8 619.1,-322.86 638.77,-322.86 v1(638.97,-323.07) ; 695.65,-465.79 700.21,-465.79 708,-458 709,-458 730.83,-436.17 ; 729.13,-409.25 729.13,-413.58 730.83,-415.27
  Top Layer w10: C34.2@28.25,-315.5 28.25,-341.09 30,-342.84 v1(30,-345) ; EC1.7@66.4,-528.32 66.4,-448.6 v1(95,-420) ; C78.2@103.59,449.25 103.74,449.1 v1(103.74,405.37) ; EC1.13@160.89,-528.32 160.94,-528.27 160.94,-464.06 v1(185,-440) ; v1(170.7,405.37) C65.2@170.7,449.1 ; v1(219.81,406.31) 219.81,408.48 224.23,412.89 224.23,435.25 C79.2@238.08,449.1 ; C35.2@232.4,-309.82 236.34,-309.82 255,-291.16 255,-261.69 270,-246.69 270,-230.4 v1(270.93,-229.47) ; EC1.19@255.38,-528.32 255.38,-451.79 270,-437.16 v1(270,-435) ; v1(297,350) 297,351.79 319.07,373.86 319.07,435.55 C66.2@305.52,449.1 ; C80.2@372.96,449.1 374,448.06 v1(374,413) ; EC1.29@412.86,-528.32 412.86,-452.14 v1(430,-435) ; C67.2@440.25,449.25 440.37,449.13 v1(475.11,449.13) 507.58,449.13 C84.2@507.7,449.25 ; EC1.35@507.34,-528.32 507.34,-458.55 515.37,-450.53 518.47,-450.53 v1(520,-449) ; C71.2@575.14,449.25 575.88,450 v1(610,450) 641.83,450 C85.2@642.58,449.25 C85.2@642.71,449.12 ; v1(673,-448) 674.53,-449.53 686.97,-449.53 695.65,-458.21 695.65,-465.79 EC1.47@695.65,-527.65 ; C72.2@709.89,449.38 C72.2@710.02,449.25 710.15,449.12 v1(710.15,413.63) ; J1.77@719.25,18.5 719.25,75.09 725,80.84 v1(725,83) ; v1(745.08,448.88) 777.09,448.88 C74.2@777.46,449.25 ; C73.2@844.9,449.25 844.9,450.24 868.14,473.47 878.47,473.47 v1(880,475) ; v1(1100,-430) 1100,-432.16 1105.77,-437.93 EC1.65@1105.77,-528.32 ; v1(1352.35,-379.5) 1352.54,-379.5 1372.95,-399.91 1372.95,-440.95 1389.31,-457.31 1389.31,-528.24 EC1.83@1389.23,-528.32 ; J1.17@1506.85,18.7 1506.85,71.61 v1(1508.33,73.09) ; EC1.97@1609.71,-528.32 1608.06,-526.68 1608.06,-464.06 1593.04,-449.04 1593.04,-421.33 1593,-421.28 1593,-404.72 1593.04,-404.67 1593.04,-396.96 v1(1615,-375) ; EC1.111@1830.18,-528.32 1830.18,-454.25 1814.62,-438.69 1814.62,-394.09 1834.07,-374.64 v1(1834.07,-372.53) ; v1(2963.53,-355) 2965,-355 2983.82,-373.82 2983.82,-435.82 3001.1,-453.1 EC2.135@3001.1,-522.97 ; v1(3287.49,-377) 3289.65,-377 3302.41,-389.75 3315.75,-389.75 3340.21,-414.21 3340.21,-445.51 3347.56,-452.85 EC2.157@3347.56,-522.97 ; v1(3693.8,-370.72) 3674,-390.52 3674,-435.97 3694.02,-455.98 EC2.179@3694.02,-522.97
  Top Layer w15: C13.2@2624.63,1265.25 2626.04,1265.25 2630.35,1269.56 2630.35,1292.12 v1(2630.92,1292.7) ; U6.3@2627.29,398.72 U6.8@2660.16,398.72 2660.28,398.61 2701.28,398.61 v1(2701.4,398.49) ; U2.3@2627.29,1352 2696.95,1352 2699.07,1349.88 v1(2699.88,1349.88) ; C11.2@2644.76,1206.95 2645.74,1206.95 2656.94,1195.74 2656.94,1194.76 2687,1164.7 2687,1079.81 2667,1059.81 v1(2667,1059)
  Top Layer w20: v1(-99.79,548.13) v1@-99.86,548.2 ; J2.A8@-99.23,227.15 v1(-99.23,322.72) -99.23,436.1 -99.86,436.73 v1@-99.86,548.2 ; J2.A1@-99.23,1679.51 v1(-99.23,1601.07) v1(-99.23,1347.03) -99.23,1223.5 -102.21,1220.53 v1(-102.21,1098.61) -100,1096.4 -100,1016.79 -99.23,1016.02 -99.23,893.58 -100,892.81 -100,801.65 -100,686.87 -99.86,686.73 v1@-99.86,548.2 ; J1.A8@257.15,139.23 336.38,139.23 337.14,140 J1.A7@466.1,140 J1.A6@716.1,140 J1.A5@923.58,140 1045.26,140 1046.02,139.23 v1(1135.15,139.23) 1253.97,139.23 1254.74,140 1366.32,140 v1(1366.67,140.35) ; J4.A8@257.15,1764.23 v1(335.58,1764.23) v1(589.63,1764.23) 716.1,1764.23 v1(837.6,1764.23) v1(1125.15,1764.23) v1(1377.03,1764.23) 1503.5,1764.23 1504.01,1763.73 v1(1628.29,1763.73) ; v1@1370,140 J1.A2@1501.34,140 ; J1.A2@1503.5,140 v1(1645,140) J1.A1@1708.74,140 ; v1@1628.93,1764.23 J4.A1@1709.51,1764.23 ; C26.2@1827.24,-300.54 C24.2@1827.24,-251.43 1828,-250.67 v1(1828,-233.78) ; J3.A1@2064.23,230.49 2064.23,436.5 2065,437.26 v1@2065,551.67 ; v1@2064.66,551.67 v1(2064.66,554.33) 2064.66,619.07 2064.23,619.49 2064.23,1016.42 2064.69,1016.87 2064.69,1100.31 2064.54,1100.46 2064.54,1223.59 2064.23,1223.9 2064.23,1473.9 J3.A7@2064.69,1474.35 ; J3.A1@2065,229.02 2065,154.67 v1(2070.4,149.27) ; J3.A7@2065,1473.9 J3.A8@2065,1681.38 ; R86.1@2288.47,753.84 R84.1@2348.47,753.84 2348.63,754 v1(2377,754) ; v1(2288.47,1737.17) R31.1@2288.47,1707.12 R29.1@2348.47,1707.12 ; v1(2355,1057.99) 2355,1067.28 2369.79,1082.07 R26.1@2369.79,1086.01 R27.1@2426.8,1086.01 ; v1(2369,94) 2369.79,94.79 R80.1@2369.79,132.73 R81.1@2426.8,132.73 ; R82.1@2480.52,132.73 2480.52,95.96 v1(2480.74,95.73) ; v1(2527.81,93.14) 2528.34,93.67 R56.2@2528.34,132.73 ; R1.2@2528.34,1086.01 2530,1084.35 v1(2530,1059.33) ; R59.1@2583,527.34 v1(2583,556.01) ; R4.1@2583.62,1480 2583.62,1504.2 2594.39,1514.98 v1(2594.39,1515.66)
  Bottom w8: U11.3@384.75,-254.63 397.2,-254.63 402.42,-249.41 v1(404.58,-249.41) ; C36.2@565,-126.38 v1(565,-85) ; U12.3@619.1,-257.76 653.86,-223 v1(700,-223) ; C7.1@2676.97,1320.83 2680.91,1320.83 2698.09,1338.01 2698.09,1348.09 2700,1350 2698.09,1351.91 2698.09,1360.3 2682.14,1376.25 C4.1@2678.2,1376.25
  Bottom w10: v1(-115,-260) -113.31,-258.31 C75.2@-66.15,-258.31 C62.2@-5,-258.31 ; v1@29.58,-344.58 v1(30,-345) ; C32.2@54,-186.38 54,-160.86 59.86,-155 84.28,-155 v1(84.89,-154.39) 104.23,-154.39 128.85,-179.02 C76.2@128.85,-180 C63.2@190,-180 ; v1(95,-420) 95,-422.16 97.9,-425.06 EC1.10@97.9,-528.32 ; v1(180,-230) 180,-227.84 187.14,-220.7 ; v1(185,-440) 185,-442.16 192.14,-449.31 192.14,-528.08 EC1.16@192.38,-528.32 ; 192.14,-220.7 C63.2@192.14,-190.16 ; v1(270,-435) 270,-435.2 286.87,-452.07 EC1.22@286.87,-528.32 ; v1(270.93,-229.47) 270.93,-196.37 C77.2@267.55,-192.99 C64.2@328.7,-192.99 342.4,-179.29 342.4,-172.91 378.19,-137.13 385,-130.32 C33.2@385,-126.38 ; C81.2@448.85,-182.83 C68.2@510,-182.83 510,-181.85 554.72,-137.13 558.19,-137.13 565,-130.32 C36.2@565,-126.38 ; v1(520,-449) 521.53,-450.53 531.17,-450.53 538.84,-458.21 EC1.38@538.84,-528.32 ; C82.2@637.04,-182.99 C69.2@698.19,-182.99 700,-184.8 v1(700,-223) ; EC1.46@664.83,-528.32 664.83,-458.21 673,-450.03 v1(673,-448) ; C83.2@780.3,-173.59 C70.2@841.45,-173.59 873.22,-173.59 877.39,-169.42 v1(877.39,-167.39) ; 2064.66,487.44 v1(2064.66,554.33) ; R88.1@2818.32,663.27 2819,663.95 v1(2819,698)
  Bottom w15: R28.1@2027.79,1301.32 2031.72,1301.32 2038.01,1295.03 2038.01,1262.74 v1(2038.1,1262.65) ; C8.2@2616.78,1158.65 C3.2@2616.78,1215.17 2621.09,1219.48 2625.03,1219.48 2647.1,1241.55 2647.1,1269.12 2648.26,1270.28 C6.1@2648.26,1273.43 2644.32,1273.43 2631.5,1286.26 2631.5,1292.12 v1(2630.92,1292.7) ; C43.1@2651,415 2654.94,415 2670.87,399.07 2700.82,399.07 v1(2701.4,398.49) ; R33.1@2877.52,1515.17 2929.17,1515.17 v1(2935,1521) 2935.81,1521 2940.81,1526 R38.1@2995,1526 ; C2.2@2953,1399 2986,1399 v1(2987,1400) 2987.81,1400 2988.81,1399 C1.2@3019,1399 ; R25.1@2967.76,1187.99 3003.99,1187.99 3017.43,1201.43 3017.43,1216.43 v1(3018,1217) 3017.95,1217.05 3017.95,1246.95 C10.2@3017.9,1247 3018.11,1247.21 3018.11,1294.42 C9.2@3018.32,1294.63
  Bottom w20: v1(1223.5,1463.89) 1248.36,1439.03 U8.3@1299.31,1439.03 ; v1@1223.5,1464.08 1248.45,1489.03 U8.4@1299.31,1489.03 ; U8.1@1299.31,1339.03 1258.33,1339.03 v1(1232.32,1365.04) 1256.31,1389.03 U8.2@1299.31,1389.03 ; v1(1357,1130.96) 1357,1110.36 C61.2@1357.56,1109.81 ; U7.2@1573.07,1109.81 v1@1671.17,1109.81 ; C60.2@1662.22,1339.03 1662.22,1303.78 1669.97,1296.03 v1(1669.97,1293.73) ; R96.2@1662.22,1389.03 1704.32,1389.03 v1(1704.62,1389.33) ; v1@1673.3,1109.81 v1(1673.3,1111.94) ; R95.2@1677.2,1072.4 R94.2@1677.2,1147.21 ; v1(2031.5,1479.76) 2043.31,1467.95 R30.1@2043.31,1448 ; v1(2128.83,675.99) 2162.89,675.99 2220.92,617.95 R85.1@2220.92,534.38 ; C5.1@2588.93,1477.02 2590.74,1478.83 2590.74,1512.01 v1(2594.39,1515.66) ; C48.2@2616.78,261.89 C47.2@2616.78,205.37 2664.04,205.37 v1(2666,207.33) ; v1(2692,78.83) 2692.17,79 2830.74,79 2875.22,123.47 R79.1@2876.2,123.47 ; R87.1@2814.93,570.02 2818.32,573.41 R88.1@2818.32,663.27 ; C42.2@2829.4,473.35 2829.53,473.48 2879.86,473.48 C41.2@2880,473.62 2911.14,473.62 v1(2926.85,457.91) ; C50.2@2830.36,318.97 C49.2@2880.36,318.97 2920.51,318.97 v1(2924.85,314.64)
  other v1: 255,-401 463,-361 521,-352 453,-326 2017.45,-312.26 714,-311 2017.08,-288.06 3763.58,-247.21 219,-224 765,-212 50,-195 24,-160 946,-151 -66,-130 20,-104 -311.42,-84.21 212,-78 248,-59.3 101,-26 266.13,-3.13 213,1 174.32,41.93 -208,54 171,94 117,106 -311.42,115.79 -102.53,118.16 14,120 828.92,140 102,175 1844.7,201.79 224,215 -210,216 188,221 109,251 2679.6,256.05 209,263 174,310 243,310 -311.42,315.79 3373,318 3416.33,318 1575,320 1854.34,322 3329,342.5 3373,342.5 108,348 1571.37,354.2 3373,367 209,373 3329,392.5 3373,392.5 1547.16,406.48 578,410 765,414 3373,417 3329,445 3373,445 3373,470 3329,495 3373,495 -311.42,515.79 3373,526 3416.33,526 2388,554 493.42,555.5 589.42,555.5 628.3,555.5 724.3,555.5 763.18,555.5 185.32,556.98 223.65,556.48 319.65,556.48 454.53,556.98 1692.86,568.9 3373,777 3416.33,777 3329,801.5 3373,801.5 3373,826 3329,851.5 3373,851.5 3373,876 3329,904 3373,904 3373,929 3129.4,946.19 3030.58,948.67 3329,954 3373,954 3373,985 3416.33,985 3031.58,1063.67 3125.58,1063.67 3401,1265 3256.58,1266.79 881,1324 3327,1326 719,1333 3256.83,1384.79 3403,1385 3126.58,1397.79 2648.45,1420.43 -300,1450 3325,1480 -151,1484 850,1484 201,1493 409,1495 2260,1494.67 605,1497 3404,1544 3251.58,1549.34 937,1558 110,1565 310,1565 510,1565 710,1565 -55,1578 3326.62,1624.38 -300,1650 -155,1653 3076,1699 3405.12,1702.88 140,1706 -228,1740 50,1743 -138,1824 146,1829 -300,1850 247,1886 1785,1896 2145,1996 -152,2002 190,2005 390,2005 590,2005 790,2005 990,2005 1190,2005 1390,2005 1647,2006
  other v2: 2416.96,347.54 2385.46,379.04 2416.96,379.04 2448.46,379.04 2416.96,410.53 2416.96,1300.82 2385.46,1332.32 2416.96,1332.32 2408.31,1362.86
HSEC_PIN9: EC1.9 R97.1 U4.1 | length 468.3
  Top Layer w4: R97.1@-66.15,-238.62 -43.42,-238.62 -41.07,-240.97 -41.07,-254 -16.14,-278.94 48.94,-278.94 61.19,-291.19 114.56,-291.19 127.93,-304.56 127.93,-310.22 125.59,-312.56 125.52,-312.56 123.59,-314.5 U4.1@123.59,-320.41 123.59,-326.31 127.22,-329.94 127.22,-439.02 108.14,-458.09 108.14,-473.78 97.9,-484.03 EC1.9@97.9,-528.32
HSEC_PIN11: EC1.11 R98.1 U4.2 | length 469.7
  Top Layer w4: R98.1@-5,-238.62 -27.73,-238.62 -30.07,-240.97 -30.07,-250.86 -11.99,-268.94 54.5,-268.94 65.75,-280.19 119.12,-280.19 138.93,-300.01 138.93,-310.22 141.27,-312.56 141.34,-312.56 143.27,-314.5 U4.2@143.27,-320.41 143.27,-326.31 138.22,-331.37 138.22,-443.57 119.14,-462.65 119.14,-473.78 129.39,-484.03 EC1.11@129.39,-528.32
HSEC_PIN12: EC1.12 R109.1 U10.1 | length 990.7
  Top Layer w4: R109.1@448.95,-163.25 470.43,-163.25 472.78,-165.6 472.78,-205.18 v1(457.44,-220.52)
  SIG1 w4.2: v1(90.84,-218.85) 90.84,-215.11 101.56,-204.39 105.51,-200.44 115.86,-200.44 118.33,-202.9 118.33,-209.97 120.16,-211.8 128.7,-211.8 130.53,-209.97 130.53,-202.27 132.36,-200.44 140.9,-200.44 142.73,-202.27 142.73,-209.97 144.56,-211.8 153.1,-211.8 154.93,-209.97 154.93,-202.9 157.39,-200.44 163.13,-200.44 192.56,-200.44 220,-173 441.34,-173 470.34,-202 470.34,-207.62 v1(457.44,-220.52)
  Bottom w4: v1(90.84,-218.85) 91.67,-219.69 117.43,-219.69 127.93,-230.19 127.93,-251.1 123.59,-255.45 U10.1@123.59,-261.35 123.59,-267.26 U10.1@125.52,-269.19 ; U10.1@125.59,-269.19 127.93,-271.54 127.93,-279.12 123.05,-284 91,-284 65,-310 65,-355 149.89,-439.89 149.89,-450.11 130.45,-469.55 130.45,-527.26 EC1.12@129.39,-528.32
HSEC_PIN14: EC1.14 R110.1 U10.2 | length 989
  Top Layer w4: v1@493.44,-220.5 482.78,-209.84 482.78,-165.1 485.12,-162.75 509.6,-162.75 R110.1@510,-163.15
  SIG1 w4.2: v1(90.84,-185.84) 94.57,-185.84 98.98,-190.24 188.33,-190.24 215.78,-162.8 445.56,-162.8 480.54,-197.78 480.54,-207.62 v1(493.44,-220.52)
  Bottom w4: v1(90.84,-185.84) 93.51,-188.51 93.51,-196.24 105.96,-208.69 121.98,-208.69 138.93,-225.63 138.93,-251.1 143.27,-255.45 U10.2@143.27,-261.35 143.27,-267.26 U10.2@141.34,-269.19 ; U10.2@141.27,-269.19 138.93,-271.54 138.93,-283.67 127.6,-295 95.56,-295 76,-314.56 76,-350.44 160.89,-435.33 EC1.14@160.89,-528.32
HSEC_PIN15: EC1.15 R99.1 U4.5 | length 438.2
  Top Layer w4: R99.1@128.85,-160.31 144.32,-160.32 152.26,-168.26 152.26,-177.1 147.26,-182.1 147.26,-251.46 143.27,-255.45 143.27,-267.26 145.21,-269.19 145.27,-269.19 147.61,-271.54 147.61,-282.3 157.69,-292.37 177.26,-292.37 195.86,-310.98 195.86,-410.86 211.56,-426.56 211.56,-455.44 203.21,-463.79 203.21,-473.21 192.38,-484.03 EC1.15@192.38,-528.32
HSEC_PIN17: EC1.17 R100.1 U4.4 | length 437.7
  Top Layer w4: R100.1@190,-160.31 165.6,-160.31 163.26,-162.66 163.26,-181.66 158.26,-186.66 158.26,-250.74 162.96,-255.45 162.96,-267.26 161.02,-269.19 160.96,-269.19 158.61,-271.54 158.61,-277.74 162.24,-281.37 181.81,-281.37 206.86,-306.42 206.86,-405.55 223.88,-422.56 EC1.17@223.88,-528.32
HSEC_PIN18: EC1.18 R111.1 U10.5 | length 977.7
  Top Layer w4: v1(434.66,-299) 447.66,-286 447.66,-269.34 460,-257 483.83,-257 511.73,-229.1 526.54,-229.1 560.43,-195.21 651.21,-195.21 662.11,-184.3 662.11,-165.65 659.77,-163.31 R111.1@637.04,-163.31
  SIG1 w4.2: v1(212.87,-255.74) 215.51,-258.38 232.11,-258.38 ccw(c243.12,-245.29) 233.8,-259.63 252.83,-278.65 444.08,-278.65 449.17,-283.75 449.17,-291.11 443.93,-296.36 437.3,-296.36 v1(434.66,-299)
  Bottom w4: U10.5@143.27,-326.31 147.05,-330.09 147.05,-368.23 223.88,-445.07 EC1.18@223.88,-528.32 ; U10.5@143.27,-320.41 143.27,-314.5 145.21,-312.56 145.27,-312.56 147.61,-310.22 147.61,-296.39 159.1,-284.9 215.94,-284.9 226,-274.84 226,-265.08 216.66,-255.74 v1(212.87,-255.74)
HSEC_PIN20: EC1.20 R112.1 U10.4 | length 979.5
  Top Layer w4: v1(470.72,-299) 470.66,-299 457.66,-286 457.66,-273.49 464.14,-267 487.97,-267 515.87,-239.1 530.69,-239.1 564.57,-205.21 655.35,-205.21 673.11,-187.45 673.11,-165.65 675.46,-163.31 R112.1@698.19,-163.31
  SIG1 w4.2: v1(243.12,-245.29) 246.75,-248.92 246.75,-258.15 257.05,-268.45 448.3,-268.45 459.37,-279.53 459.37,-287.59 v1(470.72,-299)
  Bottom w4: U10.4@162.96,-326.31 161.02,-328.25 160.96,-328.25 158.05,-331.16 158.05,-363.23 234.69,-439.87 234.69,-459.69 246.55,-471.55 246.55,-519.5 EC1.20@255.38,-528.32 ; U10.4@162.96,-320.41 162.96,-314.5 161.02,-312.56 160.96,-312.56 158.61,-310.22 158.61,-300.94 163.66,-295.9 220.49,-295.9 237,-279.39 237,-254.63 243.12,-248.52 v1(243.12,-245.29)
HSEC_PIN21: EC1.21 R101.1 U5.1 | length 447.6
  Top Layer w4: R101.1@267.55,-173.31 290.28,-173.31 292.63,-175.65 292.63,-273.18 309.76,-290.31 336.29,-290.31 345.82,-299.85 349.66,-303.69 349.66,-309.34 347.31,-311.69 347.25,-311.69 345.32,-313.62 U5.1@345.32,-319.53 345.32,-325.43 347.25,-327.37 347.31,-327.37 349.66,-329.71 349.66,-385.34 297.12,-437.88 297.12,-473.78 286.87,-484.03 EC1.21@286.87,-528.32
HSEC_PIN23: EC1.23 R102.1 U5.2 | length 447.6
  Top Layer w4: EC1.23@318.37,-528.32 318.37,-484.03 308.12,-473.78 308.12,-442.44 360.66,-389.9 360.66,-329.71 363,-327.37 363.06,-327.37 365,-325.43 U5.2@365,-319.53 365,-313.62 363.06,-311.69 363,-311.69 360.66,-309.34 360.66,-299.13 356.82,-295.29 340.84,-279.31 314.31,-279.31 303.63,-268.63 303.63,-175.65 305.97,-173.31 R102.1@328.7,-173.31
HSEC_PIN24: EC1.24 R113.1 U11.1 | length 1476.8
  Top Layer w4: R113.1@780.3,-153.91 803.03,-153.91 805.38,-156.25 805.38,-197.9 797.79,-205.49 v1(797.79,-209.28)
  SIG1 w4.2: v1(244.19,-337.63) 244.46,-337.9 244.46,-350.47 252.88,-358.9 256.38,-358.9 258.49,-358.9 260.95,-356.43 260.95,-347.3 263.39,-344.86 270.71,-344.86 273.15,-347.3 273.15,-355.46 275.59,-357.9 282.91,-357.9 285.35,-355.46 285.35,-347.3 287.79,-344.86 295.11,-344.86 297.55,-347.3 297.55,-356.43 300.01,-358.9 309.64,-358.9 345.02,-358.9 367,-380.87 367,-403.58 441.68,-478.26 556.54,-478.26 668,-366.8 707,-366.8 790.33,-283.47 790.33,-269.08 795.9,-263.51 810.39,-263.51 817.35,-256.56 817.37,-252.61 ; v1(797.79,-209.28) 800.43,-211.92 806.75,-211.92 817.4,-222.58 817.4,-248.61 ; 817.31,-252.55 817.31,-248.41
  Bottom w4: v1(244.19,-337.63) 244.19,-333.85 240,-329.66 240,-321 283,-278 283,-262 305,-240 347.31,-240 349.66,-242.34 349.66,-250.29 347.31,-252.63 347.25,-252.63 345.32,-254.57 U11.1@345.32,-260.47 345.32,-266.38 349.34,-270.41 349.34,-277.83 344.05,-283.12 320.66,-283.12 285.5,-318.28 285.5,-356.05 338.86,-409.42 338.86,-416.49 338.86,-422.73 336.46,-425.13 334.35,-425.13 331.95,-427.53 331.95,-434.73 334.35,-437.13 336.46,-437.13 338.86,-439.53 338.86,-441.54 338.86,-451.14 320.45,-469.55 320.45,-526.24 EC1.24@318.37,-528.32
